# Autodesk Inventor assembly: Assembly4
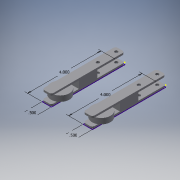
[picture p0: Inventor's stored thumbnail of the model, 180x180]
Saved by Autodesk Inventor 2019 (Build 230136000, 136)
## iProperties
Created: 2019-01
Part Number: Assembly4
Document SubType Name: Assembly
Designer: Patel Family
Author: Patel Family
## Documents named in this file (3)
- A:\Documents\Inventor Files\Assembly4.iam
- A:\Documents\Part41.ipt
- A:\Documents\Part42.ipt
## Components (4 placed, 2 different names)
1. Part41:1 — Insert:1
2. Part42:1 — Insert:1
3. Part41:2
4. Part42:2
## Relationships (1: Insert 1)
- Insert:1: Part41:1 ↔ Part42:1
## Named parameters: d1_d0 = 0
